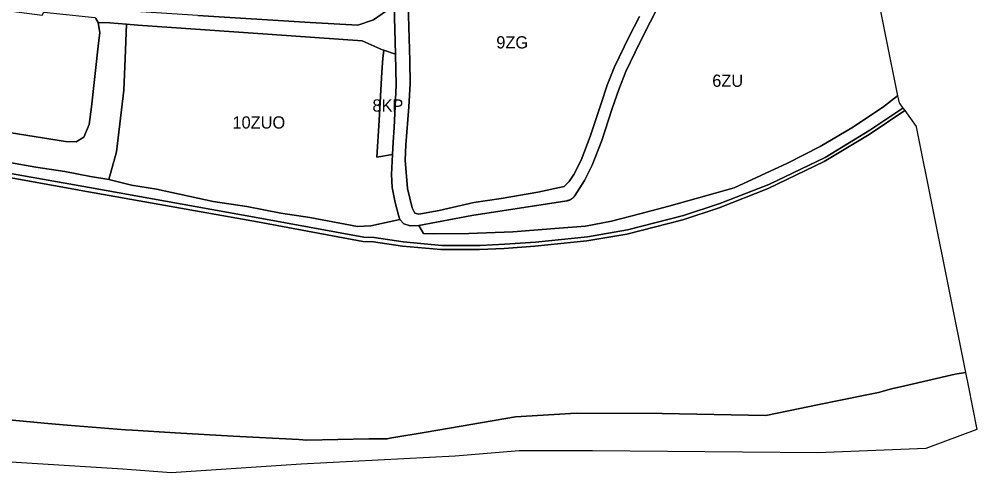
# Model space of a CAD drawing. Extents: x -300162 to -296646, y 29434 to 30761.
# Drawn here: x -297429 to -296646, y 29434 to 29805 of the extents above; entities that cross this region are included whole.
import ezdxf

# ---------------------------------------------------------------- set-up
doc = ezdxf.new("R2010")
doc.units = 0
doc.layers.add('linie_rozgraniczajace', color=7, linetype='Continuous')
doc.layers.add('oznaczenia_przeznaczen', color=7, linetype='Continuous')

msp = doc.modelspace()

# ---------------------------------------------------------------- linework, layer by layer
at = {"layer": 'linie_rozgraniczajace'}
for points in [[(-297331.83, 29813.38), (-297330.378, 29839.293), (-297327.66, 29887.78), (-297325.648, 29923.681), (-297324.9, 29937.02), (-297319.56, 29939.45), (-297289.3, 29935.77), (-297237.96, 29929.542), (-297233.155, 29928.959), (-297221.95, 29927.6), (-297214.164, 29926.843), (-297133.063, 29918.958), (-297128.6, 29811.97), (-297139.12, 29804.55), (-297151.81, 29800.41), (-297190.84, 29802.58), (-297282.65, 29808.12), (-297329.3, 29811.14)], [(-297355.48, 29674.05), (-297349.2, 29696.8), (-297343.12, 29747.1), (-297342.15, 29773.07), (-297341, 29801.15), (-297331.88, 29800.21), (-297315.935, 29799.241), (-297225.8, 29793.02), (-297148.28, 29787.5), (-297131.1, 29779.92), (-297130.611, 29779.757), (-297131.543, 29772.957), (-297132.247, 29762.219), (-297134.418, 29722.29), (-297136.237, 29692.307), (-297123.593, 29694.596), (-297124.4, 29678.2), (-297123.7, 29667.6), (-297121.4, 29655.25), (-297118.524, 29644.849), (-297117.57, 29641.4), (-297141.3, 29636.05), (-297152.08, 29635.6), (-297191.25, 29643.08), (-297214.88, 29646.5), (-297242.68, 29652), (-297270.15, 29656.1), (-297316.5, 29666.15), (-297336.9, 29669.38), (-297352.101, 29673.201)], [(-297136.237, 29692.307), (-297134.418, 29722.29), (-297132.247, 29762.219), (-297131.543, 29772.957), (-297130.611, 29779.757), (-297121.15, 29776.6), (-297120.7, 29751.2), (-297122.2, 29716.5), (-297123.1, 29704.6), (-297123.593, 29694.596)]]:
    msp.add_lwpolyline(points, close=True, dxfattribs=at)
for points in [[(-296729.718, 29837.66), (-296710.569, 29742.447), (-296723.02, 29732.97), (-296748.15, 29716.41), (-296773.89, 29701.04), (-296800.62, 29687.3), (-296844.21, 29667.12), (-296897.7, 29652.24), (-296921.45, 29645.99), (-296944.43, 29640.04), (-296965.83, 29635.79), (-296990.75, 29633.93), (-297025.09, 29631.26), (-297061.11, 29629.83), (-297089.77, 29629.51), (-297098.137, 29629.936), (-297102.1, 29636.3), (-297058.6, 29644.45), (-296986.239, 29655.803), (-296981.153, 29656.601), (-296980.956, 29656.634), (-296980.759, 29656.671), (-296980.563, 29656.712), (-296980.368, 29656.757), (-296980.174, 29656.805), (-296979.981, 29656.858), (-296979.789, 29656.914), (-296979.599, 29656.974), (-296979.409, 29657.038), (-296979.221, 29657.106), (-296979.034, 29657.178), (-296978.849, 29657.253), (-296978.665, 29657.332), (-296978.483, 29657.414), (-296978.303, 29657.501), (-296978.124, 29657.59), (-296977.947, 29657.684), (-296977.772, 29657.781), (-296977.599, 29657.881), (-296977.428, 29657.985), (-296977.259, 29658.092), (-296977.093, 29658.203), (-296976.928, 29658.316), (-296976.766, 29658.434), (-296976.606, 29658.554), (-296976.449, 29658.677), (-296976.294, 29658.804), (-296976.142, 29658.934), (-296975.992, 29659.066), (-296975.845, 29659.202), (-296975.701, 29659.341), (-296975.56, 29659.482), (-296975.421, 29659.626), (-296975.286, 29659.773), (-296975.153, 29659.923), (-296975.024, 29660.075), (-296974.897, 29660.23), (-296974.774, 29660.388), (-296974.653, 29660.547), (-296974.536, 29660.71), (-296974.422, 29660.874), (-296974.312, 29661.041), (-296974.275, 29661.099), (-296966.59, 29673.135), (-296960.236, 29685.895), (-296952.494, 29705.867), (-296943.848, 29732.265), (-296938.644, 29747.739), (-296932.928, 29762.308), (-296921.464, 29786.088), (-296912.798, 29802.701), (-296905.704, 29816.658)], [(-297122.15, 29816.8), (-297121.15, 29776.6), (-297130.611, 29779.757), (-297131.1, 29779.92), (-297148.28, 29787.5), (-297225.8, 29793.02), (-297315.935, 29799.241), (-297331.88, 29800.21), (-297341, 29801.15), (-297354.734, 29802.145), (-297354.761, 29802.147), (-297364.28, 29802.43), (-297366.02, 29805.88)], [(-296974.536, 29660.71), (-296974.653, 29660.547), (-296974.774, 29660.388), (-296974.897, 29660.23), (-296975.024, 29660.075), (-296975.153, 29659.923), (-296975.286, 29659.773), (-296975.421, 29659.626), (-296975.56, 29659.482), (-296975.701, 29659.341), (-296975.845, 29659.202), (-296975.992, 29659.066), (-296976.142, 29658.934), (-296976.294, 29658.804), (-296976.449, 29658.677), (-296976.606, 29658.554), (-296976.766, 29658.434), (-296976.928, 29658.316), (-296977.093, 29658.203), (-296977.259, 29658.092), (-296977.428, 29657.985), (-296977.599, 29657.881), (-296977.772, 29657.781), (-296977.947, 29657.684), (-296978.124, 29657.59), (-296978.303, 29657.501), (-296978.483, 29657.414), (-296978.665, 29657.332), (-296978.849, 29657.253), (-296979.034, 29657.178), (-296979.221, 29657.106), (-296979.409, 29657.038), (-296979.599, 29656.974), (-296979.789, 29656.914), (-296979.981, 29656.858), (-296980.174, 29656.805), (-296980.368, 29656.757), (-296980.563, 29656.712), (-296980.759, 29656.671), (-296980.956, 29656.634), (-296981.153, 29656.601), (-296986.239, 29655.803), (-297058.6, 29644.45), (-297102.1, 29636.3), (-297109.1, 29636.2), (-297114.402, 29637.698), (-297117.57, 29641.4), (-297118.524, 29644.849), (-297121.4, 29655.25), (-297123.7, 29667.6), (-297124.4, 29678.2), (-297123.593, 29694.596), (-297123.1, 29704.6), (-297122.2, 29716.5), (-297120.7, 29751.2), (-297121.15, 29776.6), (-297122.15, 29816.8)], [(-297110.62, 29817.52), (-297109.29, 29771.26), (-297109.02, 29752.42), (-297110.12, 29733.37), (-297112.6, 29702.35), (-297113.331, 29689.818), (-297111.22, 29666.65), (-297107.58, 29650.86), (-297105.44, 29646.5), (-297102.14, 29645.54), (-297085.29, 29648.77), (-297057.1, 29655.3), (-297034.65, 29658.45), (-297004.7, 29663.55), (-296983.334, 29668.281), (-296979.229, 29672.474), (-296975.217, 29678.245), (-296969.393, 29689.94), (-296961.914, 29709.233), (-296953.339, 29735.415), (-296948.044, 29751.161), (-296942.1, 29766.312), (-296930.403, 29790.572), (-296921.689, 29807.279)], [(-296921.689, 29807.279), (-296930.403, 29790.572), (-296942.1, 29766.312), (-296948.044, 29751.161), (-296953.339, 29735.415), (-296961.914, 29709.233), (-296969.393, 29689.94), (-296975.217, 29678.245), (-296979.229, 29672.474), (-296983.334, 29668.281), (-297004.7, 29663.55), (-297034.65, 29658.45), (-297057.1, 29655.3), (-297085.29, 29648.77), (-297102.14, 29645.54), (-297105.44, 29646.5), (-297107.58, 29650.86), (-297111.22, 29666.65), (-297113.331, 29689.818), (-297112.6, 29702.35), (-297110.12, 29733.37), (-297109.02, 29752.42), (-297109.29, 29771.26), (-297110.62, 29817.52)], [(-296905.704, 29816.658), (-296912.798, 29802.701), (-296921.464, 29786.088), (-296932.928, 29762.308), (-296938.644, 29747.739), (-296943.848, 29732.265), (-296952.494, 29705.867), (-296960.236, 29685.895), (-296966.59, 29673.135), (-296974.275, 29661.099), (-296974.312, 29661.041), (-296974.422, 29660.874), (-296974.536, 29660.71)], [(-297454.12, 29814.24), (-297410.06, 29808.44), (-297408.74, 29811.08), (-297366.96, 29806.51), (-297366.02, 29805.88), (-297364.28, 29802.43), (-297362.88, 29794.13), (-297363.84, 29785.56), (-297369.7, 29733.54), (-297371.58, 29719.01), (-297375.95, 29708.67), (-297382.09, 29704.83), (-297390.88, 29705.09), (-297480.15, 29719.3)], [(-297282.65, 29808.12), (-297190.84, 29802.58), (-297151.81, 29800.41), (-297139.12, 29804.55), (-297128.6, 29811.97)], [(-297480.15, 29719.3), (-297390.88, 29705.09), (-297382.09, 29704.83), (-297375.95, 29708.67), (-297371.58, 29719.01), (-297369.7, 29733.54), (-297363.84, 29785.56), (-297362.88, 29794.13), (-297364.28, 29802.43), (-297354.761, 29802.147), (-297354.734, 29802.145), (-297341, 29801.15), (-297342.15, 29773.07), (-297343.12, 29747.1), (-297349.2, 29696.8), (-297355.48, 29674.05), (-297370.5, 29676.53), (-297391.43, 29680.48), (-297415.28, 29684.09), (-297436.71, 29688.07)], [(-297270.15, 29656.1), (-297242.68, 29652), (-297214.88, 29646.5), (-297191.25, 29643.08), (-297152.08, 29635.6), (-297141.3, 29636.05), (-297117.57, 29641.4), (-297114.402, 29637.698), (-297109.1, 29636.2), (-297102.1, 29636.3), (-297098.137, 29629.936), (-297089.77, 29629.51), (-297061.11, 29629.83), (-297025.09, 29631.26), (-296990.75, 29633.93), (-296965.83, 29635.79), (-296944.43, 29640.04), (-296921.45, 29645.99), (-296897.7, 29652.24), (-296844.21, 29667.12), (-296800.62, 29687.3), (-296773.89, 29701.04), (-296748.15, 29716.41), (-296723.02, 29732.97), (-296710.569, 29742.447), (-296709.448, 29736.872), (-296706.271, 29732.464), (-296733.211, 29714.272), (-296769.935, 29692.157), (-296815.84, 29670.042), (-296855.855, 29654.278), (-296885.65, 29644.52), (-296931.324, 29632.74), (-296964.063, 29627.197), (-297006.619, 29622.809), (-297031.679, 29621.019), (-297051.809, 29620.095), (-297083.358, 29620.095), (-297114.77, 29623.04), (-297138.473, 29626.547), (-297147.12, 29626.8), (-297233.391, 29642.737), (-297371.4, 29667.394), (-297457.662, 29682.806)], [(-297458.287, 29679.362), (-297372.015, 29663.949), (-297234.017, 29639.294), (-297147.756, 29623.358), (-297139.109, 29623.106), (-297115.406, 29619.598), (-297083.994, 29616.653), (-297052.445, 29616.653), (-297032.315, 29617.577), (-297007.255, 29619.367), (-296964.699, 29623.755), (-296931.96, 29629.299), (-296886.286, 29641.078), (-296856.491, 29650.836), (-296816.476, 29666.6), (-296770.571, 29688.715), (-296733.847, 29710.83), (-296704.811, 29730.438), (-296700.134, 29723.948), (-296695.336, 29717.29), (-296695.328, 29717.249), (-296655.153, 29516.248), (-296663.586, 29514.806), (-296704.694, 29505.2), (-296715.568, 29502.659), (-296726.111, 29499.835), (-296738.615, 29497.218), (-296774.692, 29489.909), (-296799.908, 29484.801)], [(-297457.662, 29682.806), (-297371.4, 29667.394), (-297233.391, 29642.737), (-297147.12, 29626.8), (-297138.473, 29626.547), (-297114.77, 29623.04), (-297083.358, 29620.095), (-297051.809, 29620.095), (-297031.679, 29621.019), (-297006.619, 29622.809), (-296964.063, 29627.197), (-296931.324, 29632.74), (-296885.65, 29644.52), (-296855.855, 29654.278), (-296815.84, 29670.042), (-296769.935, 29692.157), (-296733.211, 29714.272), (-296706.271, 29732.464), (-296704.811, 29730.438), (-296733.847, 29710.83), (-296770.571, 29688.715), (-296816.476, 29666.6), (-296856.491, 29650.836), (-296886.286, 29641.078), (-296931.96, 29629.299), (-296964.699, 29623.755), (-297007.255, 29619.367), (-297032.315, 29617.577), (-297052.445, 29616.653), (-297083.994, 29616.653), (-297115.406, 29619.598)], [(-297436.71, 29688.07), (-297415.28, 29684.09), (-297391.43, 29680.48), (-297370.5, 29676.53), (-297355.48, 29674.05), (-297352.101, 29673.201), (-297336.9, 29669.38), (-297316.5, 29666.15), (-297270.15, 29656.1)], [(-297115.406, 29619.598), (-297139.109, 29623.106), (-297147.756, 29623.358), (-297234.017, 29639.294), (-297372.015, 29663.949), (-297458.287, 29679.362)], [(-297495.404, 29482.761), (-297405.231, 29474.318), (-297389.576, 29473.005), (-297341.727, 29469.263), (-297336.052, 29468.895), (-297301.361, 29466.675), (-297253.7, 29464.077), (-297200.04, 29461.295), (-297193.701, 29460.685), (-297142.812, 29461.732), (-297128.018, 29461.938), (-297125.682, 29462.334), (-297095.995, 29467.373), (-297023.123, 29479.741), (-296973.34, 29482.862), (-296903.202, 29482.436), (-296818.373, 29480.909), (-296799.908, 29484.801), (-296774.692, 29489.909), (-296738.615, 29497.218), (-296726.111, 29499.835), (-296715.568, 29502.659), (-296704.694, 29505.2), (-296663.586, 29514.806), (-296655.153, 29516.248), (-296653.016, 29505.559), (-296645.83, 29469.607), (-296687.6, 29454), (-296776.05, 29450.5), (-296960, 29452), (-297019.95, 29452.1), (-297072.45, 29447.6), (-297198.3, 29441.15), (-297304.56, 29434), (-297343.9, 29437.13), (-297510, 29447.37)], [(-296799.908, 29484.801), (-296818.373, 29480.909), (-296903.202, 29482.436), (-296973.34, 29482.862), (-297023.123, 29479.741), (-297095.995, 29467.373), (-297125.682, 29462.334), (-297128.018, 29461.938), (-297142.812, 29461.732), (-297193.701, 29460.685), (-297200.04, 29461.295), (-297253.7, 29464.077), (-297301.361, 29466.675), (-297336.052, 29468.895), (-297341.727, 29469.263), (-297389.576, 29473.005), (-297405.231, 29474.318), (-297495.404, 29482.761)]]:
    msp.add_lwpolyline(points, dxfattribs=at)

# ---------------------------------------------------------------- texts
at = {"layer": 'oznaczenia_przeznaczen'}
for s, p in [('9ZG', (-297038.701459, 29781.260001)), ('6ZU', (-296862.147201, 29749.870001)), ('8KP', (-297139.968561, 29729.590001)), ('10ZUO', (-297254.393159, 29715.710001))]:
    msp.add_text(s, height=10, dxfattribs=at).set_placement(p)

doc.saveas('drawing.dxf')
